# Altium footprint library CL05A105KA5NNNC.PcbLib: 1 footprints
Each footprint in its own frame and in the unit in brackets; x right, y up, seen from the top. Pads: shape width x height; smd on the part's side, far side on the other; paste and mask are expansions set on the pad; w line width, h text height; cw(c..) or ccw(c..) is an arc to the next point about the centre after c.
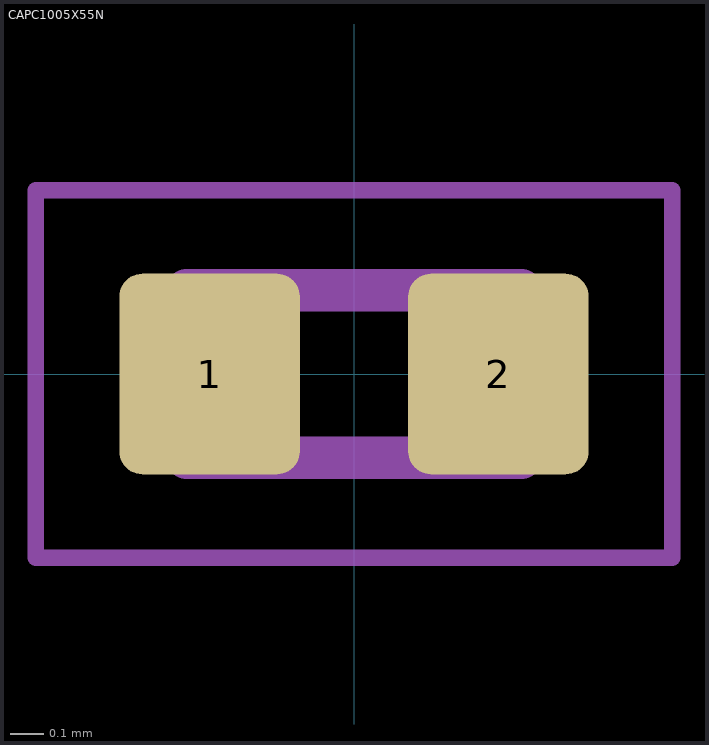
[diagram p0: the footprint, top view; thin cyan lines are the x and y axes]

## CAPC1005X55N [mm]
pads (2):
  rrect25% 0.54x0.6 smd paste+0 mask+0.102: 1(-0.432,0) 2(0.432,0)
Assembly Top:
  lines w0.127: -0.5,-0.25 0.5,-0.25 0.5,0.25 -0.5,0.25 -0.5,-0.25
Courtyard Top:
  lines w0.05: -0.952,-0.55 0.952,-0.55 0.952,0.55 -0.952,0.55 -0.952,-0.55
3D body "step_temp.STEP": height 0.55, standoff 0, extent -0.5,-0.25 0.5,0.25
